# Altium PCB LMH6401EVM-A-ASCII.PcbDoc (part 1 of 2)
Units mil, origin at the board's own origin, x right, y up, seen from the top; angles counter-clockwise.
Board outline 1307 x 2660 mil, 6 copper layers (Top Layer L1, Layer 2 GND L2, Layer 3 V+ L3, Layer 4 V- L4, Layer 5 GND L5, Bottom Layer L6), stack 56.6 mil thick; 69 components, 33 nets, 203 pads, 373 vias.
Unrouted connection lines stored in the file: 2.
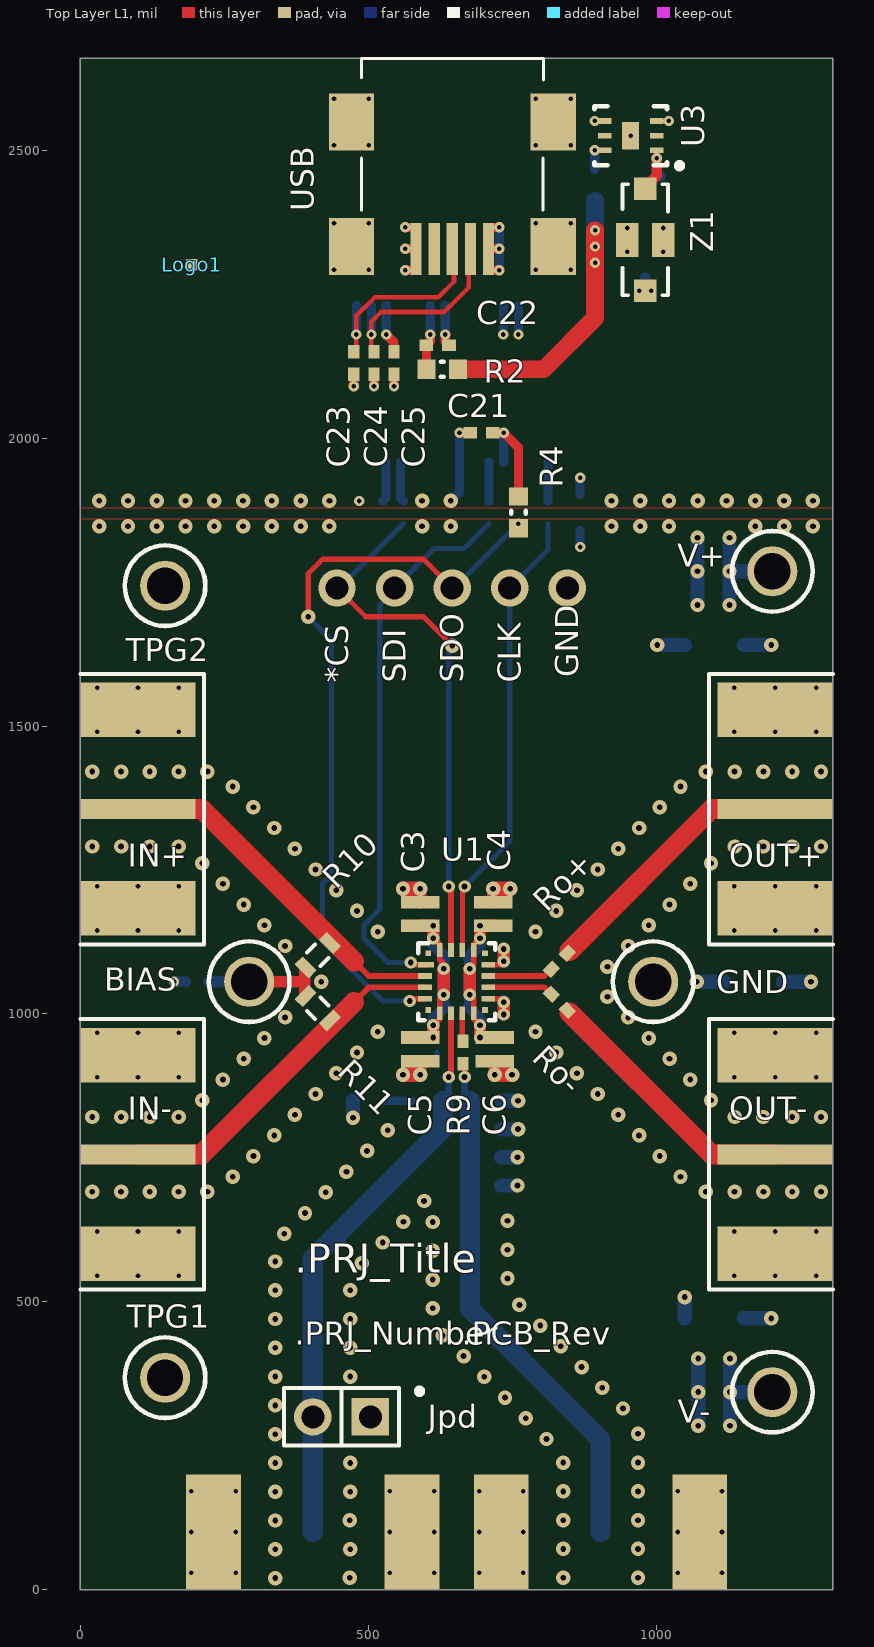
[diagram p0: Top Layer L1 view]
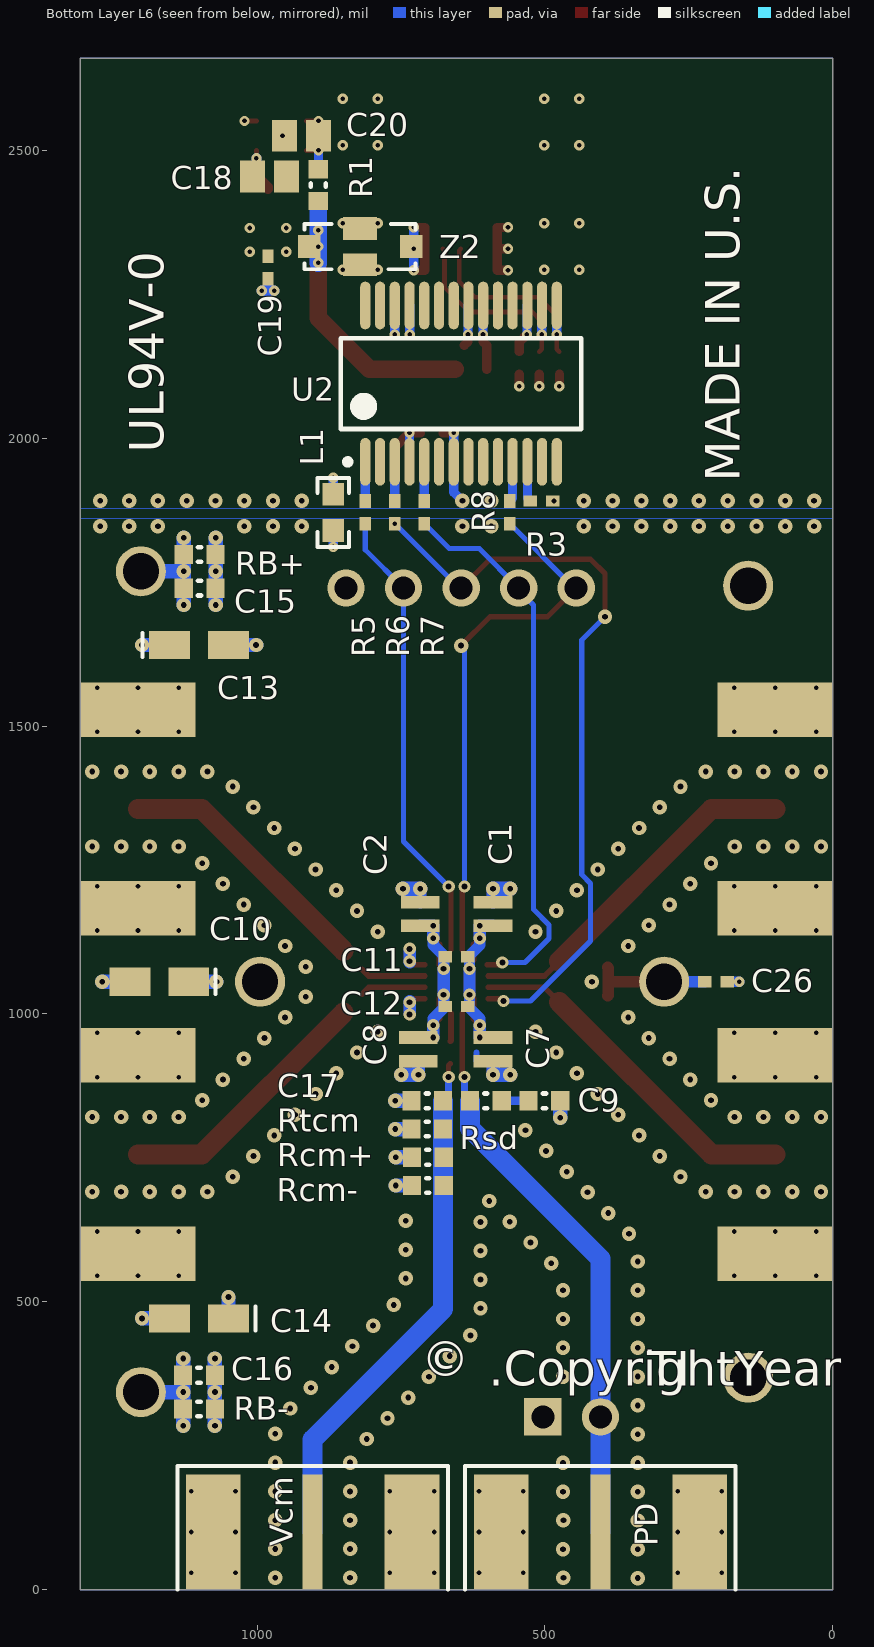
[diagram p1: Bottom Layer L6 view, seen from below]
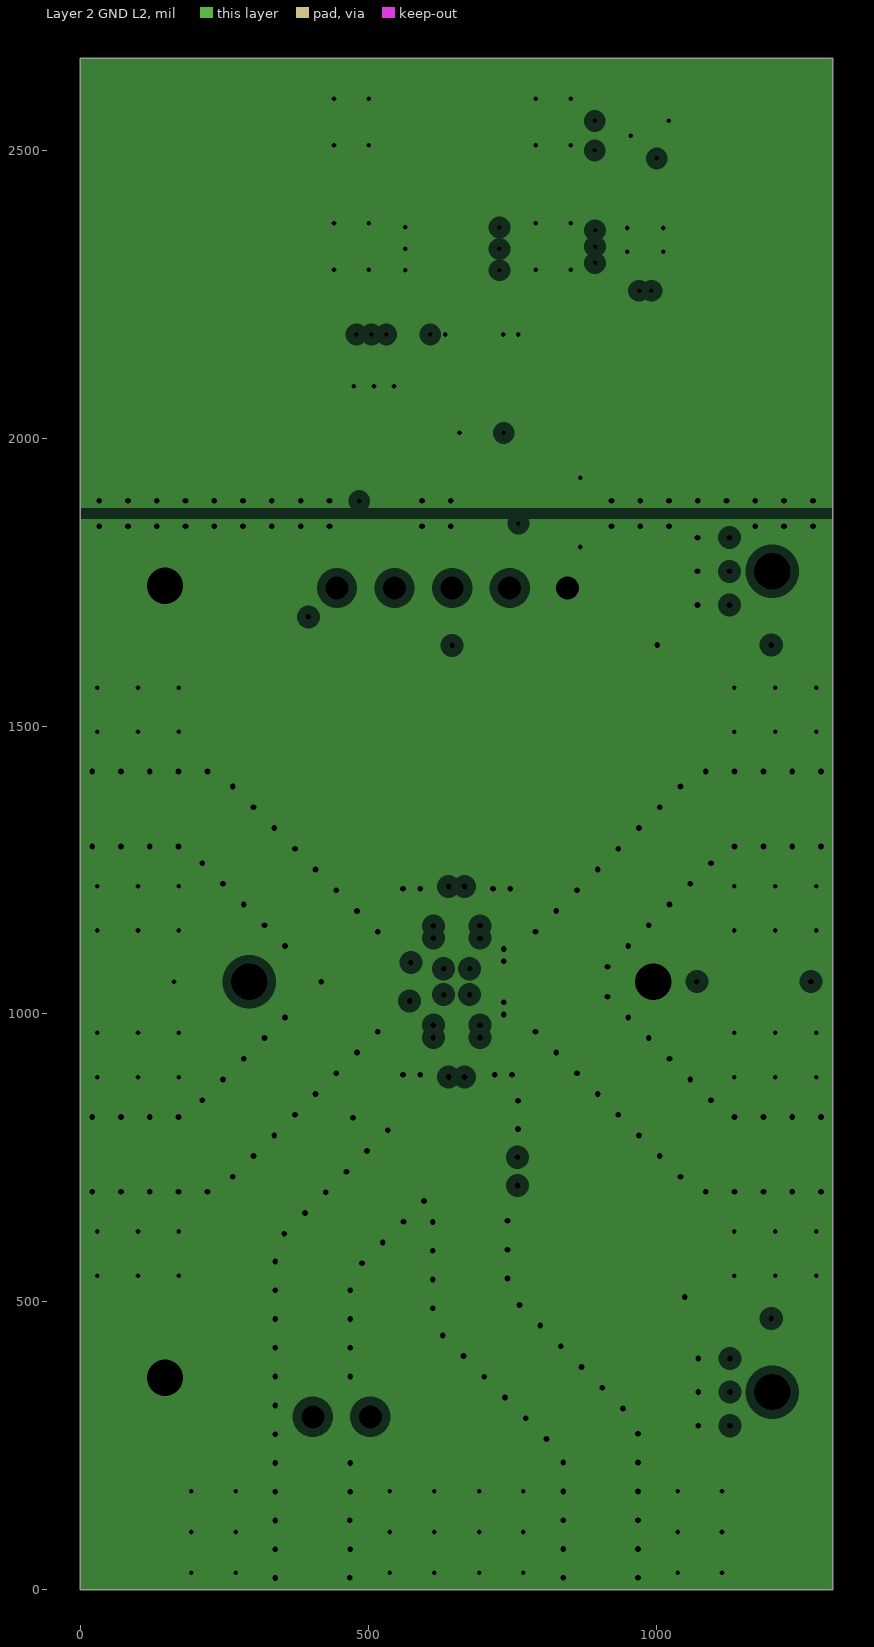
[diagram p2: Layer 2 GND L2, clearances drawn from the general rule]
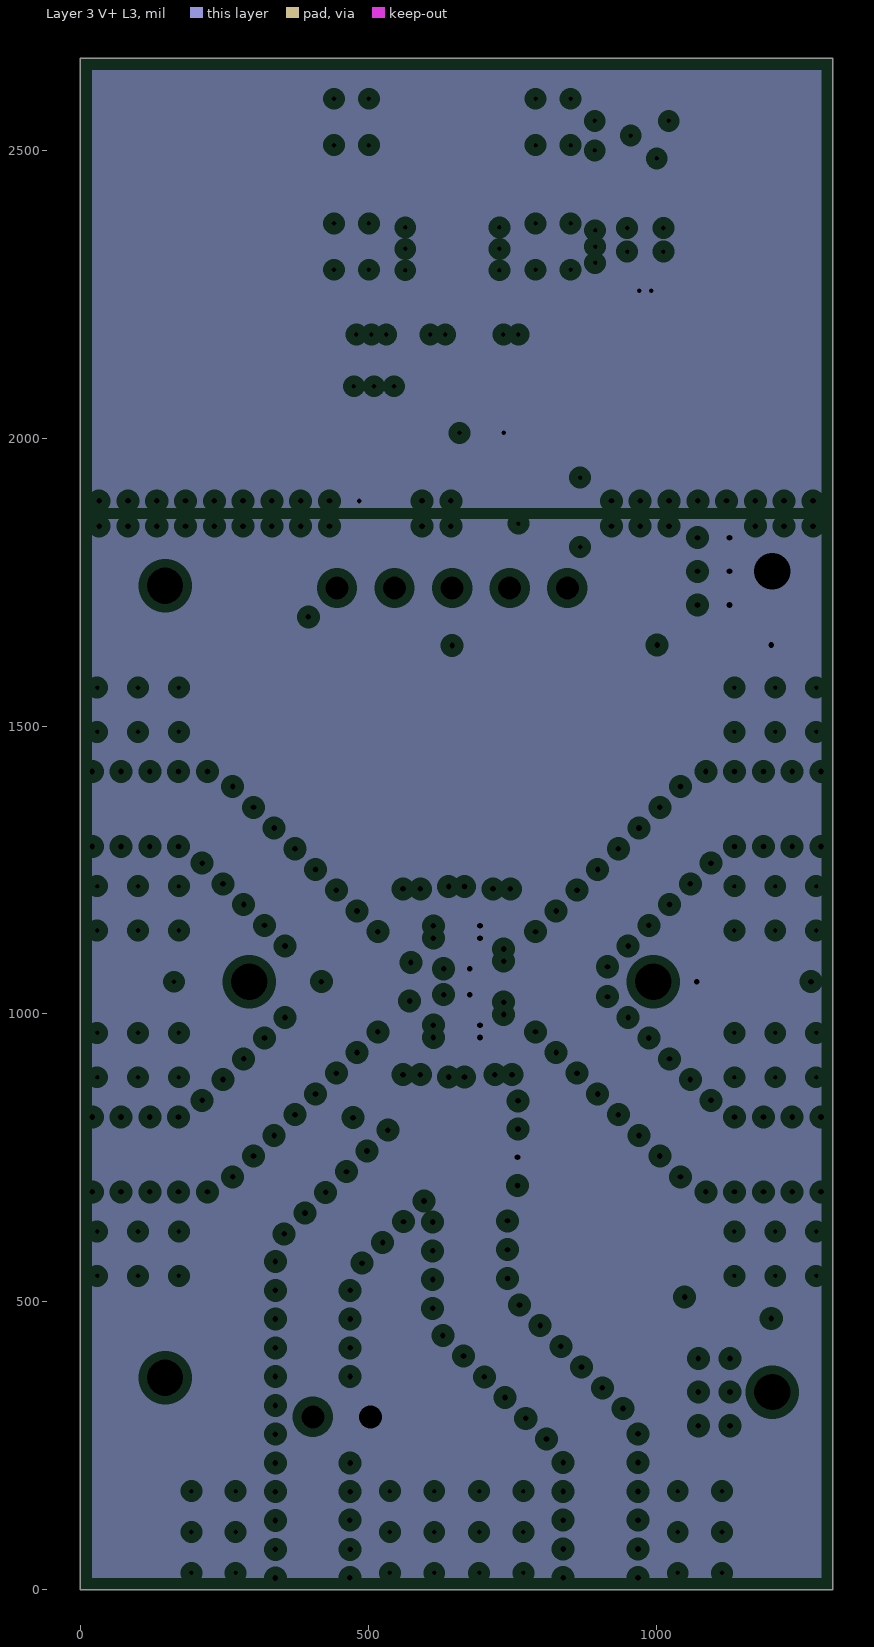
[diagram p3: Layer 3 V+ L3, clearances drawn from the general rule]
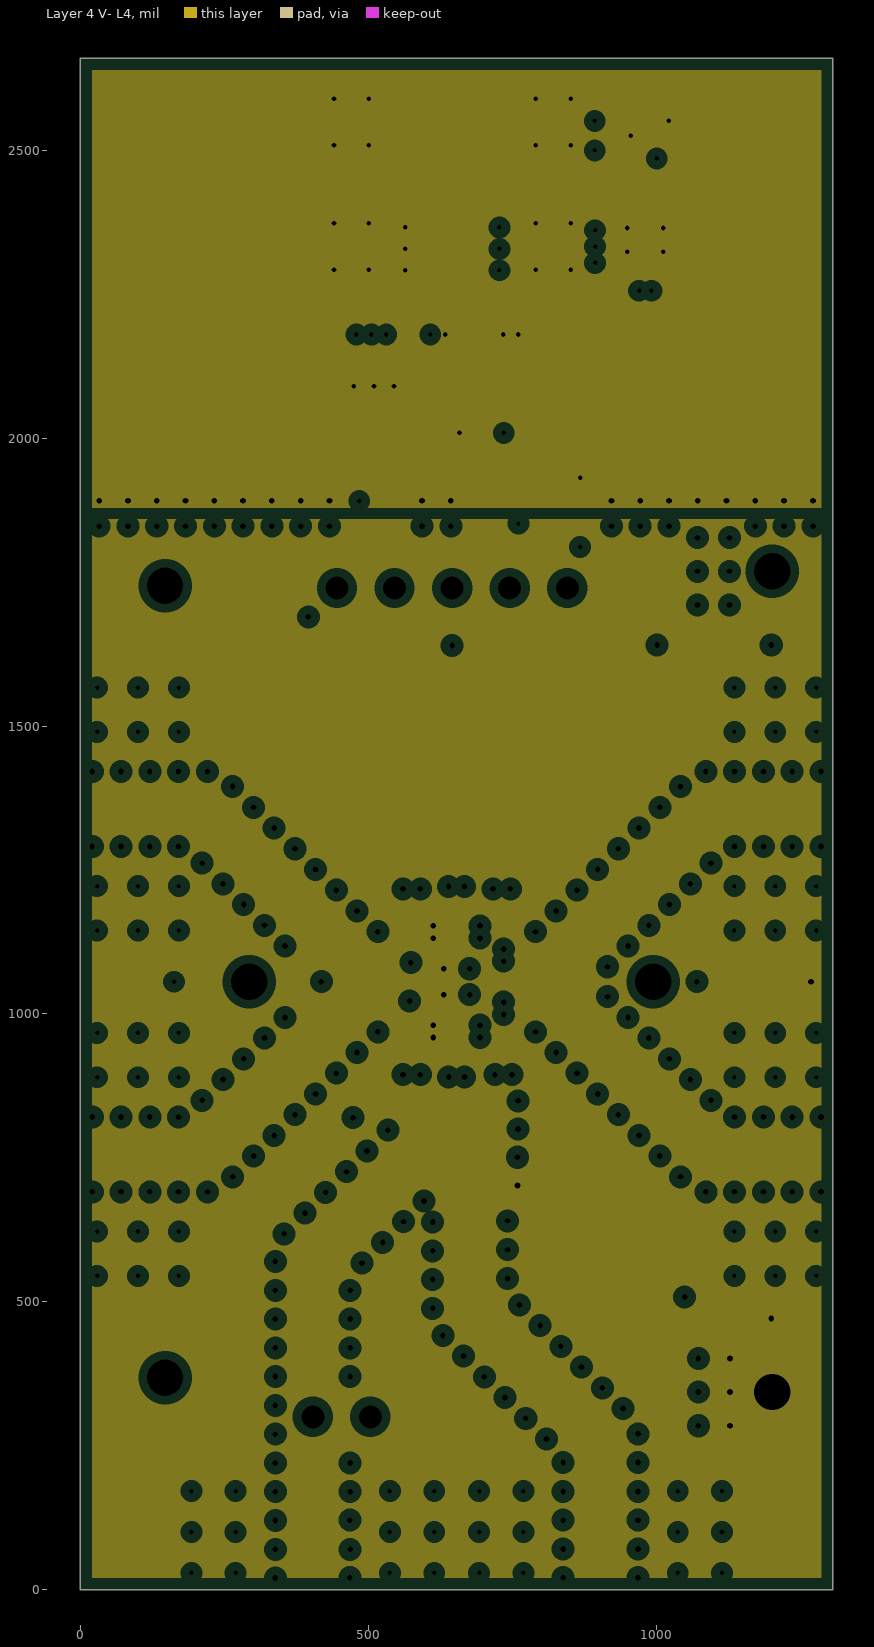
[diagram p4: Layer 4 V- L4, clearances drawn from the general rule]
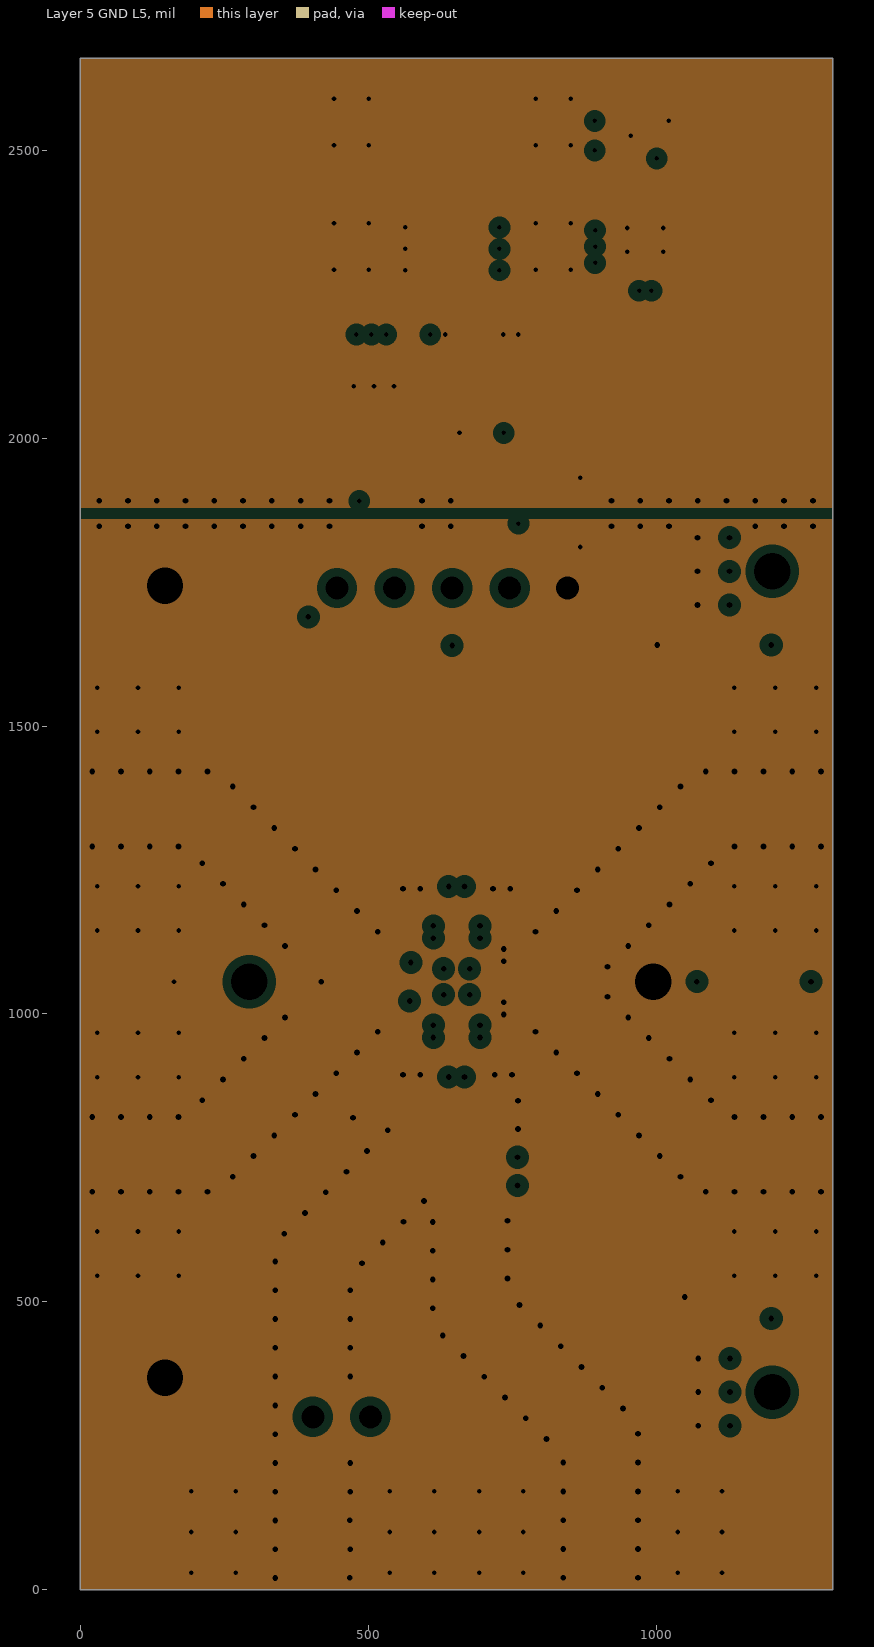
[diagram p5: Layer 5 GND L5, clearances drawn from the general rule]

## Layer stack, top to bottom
Top Solder: solder mask 0.4, Solder Resist, Dk 3.5
Top Layer L1: signal copper 1.4
Dielectric1: core 16.6, Rogers RO4350, Dk 3.66
Layer 2 GND L2: plane copper 1.4, net (Multiple Nets)
Dielectric2: prepreg 5, FR406, Dk 4.8
Layer 3 V+ L3: plane copper 1.4, net (Multiple Nets)
Dielectric4: core 5, FR406, Dk 4.8
Layer 4 V- L4: plane copper 1.4, net (Multiple Nets)
Dielectric5: prepreg 5, FR406, Dk 4.8
Layer 5 GND L5: plane copper 1.4, net (Multiple Nets)
Dielectric3: core 16.6, FR406, Dk 4.8
Bottom Layer L6: signal copper 1.4
Bottom Solder: solder mask 0.4, Solder Resist, Dk 3.5

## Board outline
0,0 1307,0 1307,2660 0,2660

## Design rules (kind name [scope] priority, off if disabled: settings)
AcuteAngle [All] p0: scope1count=1 scope1_0_kind=Board scope1_0_value=Board scope2count=1 scope2_0_kind=Board scope2_0_value=Board commentlength=0 minimum=4.50000000000000E+0001
AcuteAngle [All] p1: minimum=4.50000000000000E+0001 checktracksonly=FALSE
AssemblyTestPointUsage [All] p0: scope1count=1 scope1_0_kind=Board scope1_0_value=Board scope2count=1 scope2_0_kind=Board scope2_0_value=Board commentlength=0
AssemblyTestPointUsage [All] p1: valid=2
AssemblyTestpoint [All] p0: scope1count=1 scope1_0_kind=Board scope1_0_value=Board scope2count=1 scope2_0_kind=Board scope2_0_value=Board commentlength=0
Clearance Clearance_1 [All] p0 off: scope1count=1 scope1_0_kind=Board scope1_0_value=Board scope2count=1 scope2_0_kind=Board scope2_0_value=Board commentlength=145 gap=35 // Protel DXP Scope 2 Expression Was: (InNet('NetIN+_1') OR InNet('NetIN-_1') OR InNet('NetOUT-_1') OR InNet('NetOUT+_1') OR InNet('NetRtcm_1'))
Clearance Clearance_BoardEdge_MountingHoles [All] p0 off: scope1count=1 scope1_0_kind=Board scope1_0_value=Board scope2count=1 scope2_0_kind=Board scope2_0_value=Board commentlength=48 gap=40 // Protel DXP Scope 2 Expression Was: IsKeepOut
Clearance Clearance_BoardEdge_Poly [All] p0 off: scope1count=1 scope1_0_kind=Board scope1_0_value=Board scope2count=1 scope2_0_kind=Board scope2_0_value=Board commentlength=48 gap=25 // Protel DXP Scope 2 Expression Was: IsKeepOut
Clearance Clearance_BoardEdge [All] p0 off: scope1count=1 scope1_0_kind=Board scope1_0_value=Board scope2count=1 scope2_0_kind=Board scope2_0_value=Board commentlength=48 gap=75 // Protel DXP Scope 2 Expression Was: IsKeepOut
Clearance Clearance_Poly [All] p0 off: scope1count=1 scope1_0_kind=Board scope1_0_value=Board scope2count=1 scope2_0_kind=Board scope2_0_value=Board commentlength=48 gap=10 // Protel DXP Scope 1 Expression Was: InPolygon
Clearance [All] p0: scope1count=1 scope1_0_kind=Board scope1_0_value=Board scope2count=1 scope2_0_kind=Board scope2_0_value=Board commentlength=0 gap=5
Clearance Clearance_U2 [All] p0: scope1count=1 scope1_0_kind=Component scope1_0_value=U2 scope2count=1 scope2_0_kind=Board scope2_0_value=Board commentlength=0 gap=7.87
Clearance Clearance_2 [All] p0 off: scope1count=1 scope1_0_kind=Board scope1_0_value=Board scope2count=1 scope2_0_kind=Net scope2_0_value=NetJpd_2 commentlength=78 gap=35 // Protel DXP Scope 1 Expression Was: (InNamedPolygon('Bottom Layer L6-GND'))
Clearance Clearance_2 [(InNamedPolygon('Bottom Layer L6-GND')) vs InNet('NetJpd_2')] p1: gap=35
Clearance Clearance_1 [InNamedPolygon('Top Layer L1-GND') vs (InNet('NetIN+_1') OR InNet('NetIN-_1') OR InNet('NetOUT-_1') OR InNet('NetOUT+_1') OR InNet('NetRtcm_1'))] p2: gap=35
Clearance Clearance_U2 [InComponent('U2')] p3: gap=7.87
Clearance Clearance_BoardEdge_MountingHoles [OnCopper and InComponentClass('Mounting Holes') vs IsKeepOut] p4: gap=40
Clearance Clearance_BoardEdge_Poly [OnCopper and InPoly vs IsKeepOut] p5: gap=25
Clearance Clearance_BoardEdge [OnCopper and Not InComponentClass('Logo') and not InComponentClass('FiducialMark') and not InRegion(1000,500,4000,800) and Not IsKeepout vs IsKeepOut] p6: gap=75
Clearance Clearance_Poly [InPolygon] p7: gap=10
Clearance [All] p8: gap=5
ComponentClearance ComponentClearance_1 [All] p0 off: scope1count=1 scope1_0_kind=Board scope1_0_value=Board scope2count=1 scope2_0_kind=Board scope2_0_value=Board commentlength=188 gap=0 collisioncheckmode=3 // Protel DXP Scope 2 Expression Was: HasFootprint ('Emerson_142-0701-851*') or HasFootprint ('Keystone_1902C*') or HasFootprint ('NY PMS 440 0025 PH*') or HasFootprint ('Fiducial10-20*')
ComponentClearance ComponentClearance_Shunt [All] p0: scope1count=1 scope1_0_kind=ComponentClass scope1_0_value=Header scope2count=1 scope2_0_kind=ComponentClass scope2_0_value=Shunt commentlength=0 gap=0 collisioncheckmode=3
ComponentClearance ComponentClearance_Logo [All] p0: scope1count=1 scope1_0_kind=ComponentClass scope1_0_value=Logo scope2count=1 scope2_0_kind=Board scope2_0_value=Board commentlength=0 gap=50 collisioncheckmode=3
ComponentClearance ComponentClearance_ScrewToNut [All] p0 off: scope1count=1 scope1_0_kind=Board scope1_0_value=Board scope2count=1 scope2_0_kind=Board scope2_0_value=Board commentlength=71 gap=5 collisioncheckmode=3 // Protel DXP Scope 2 Expression Was: (HasFootprint('Keystone_1902C'))
ComponentClearance ComponentClearance_MountingHoles [All] p0: scope1count=1 scope1_0_kind=ComponentClass scope1_0_value="Mounting Holes" scope2count=1 scope2_0_kind=Board scope2_0_value=Board commentlength=0 gap=250 collisioncheckmode=3
ComponentClearance ComponentClearance_SmallPassives [All] p0 off: scope1count=1 scope1_0_kind=Board scope1_0_value=Board scope2count=1 scope2_0_kind=Board scope2_0_value=Board commentlength=620 gap=10 collisioncheckmode=3 // Protel DXP Scope 2 Expression Was: HasFootprint('0201*') or HasFootprint('0402*') or HasFootprint('0508') or HasFootprint('0603*') or HasFootprint('0612') or HasFootprint('0805*') or HasFootprint('0815*') or HasFootprint('0830*') or HasFootprint('1206*') or HasFootprint('1210*') or HasFootprint('1808*') or HasFootprint('1812*') or HasFootprint('1825*') or HasFootprint('2010*') or HasFootprint('2220*') or HasFootprint('2225*') or HasFootprint('2512*') or HasFootprint('2728*') or HasFootprint('3518*') or HasFootprint('FIL_NFM41P*') or HasFootprint('SDB06A*') or HasFootprint('0306*') or HasFootprint('RMZ0016A*')
ComponentClearance ComponentClearance_THtoSMT [All] p0 off: scope1count=1 scope1_0_kind=Board scope1_0_value=Board scope2count=1 scope2_0_kind=Board scope2_0_value=Board commentlength=53 gap=10 collisioncheckmode=3 // Protel DXP Scope 2 Expression Was: IsSMTComponent
ComponentClearance ComponentClearance_THtoTH [All] p0 off: scope1count=1 scope1_0_kind=Board scope1_0_value=Board scope2count=1 scope2_0_kind=Board scope2_0_value=Board commentlength=54 gap=75 collisioncheckmode=3 // Protel DXP Scope 2 Expression Was: IsThruComponent
ComponentClearance [All] p0: scope1count=1 scope1_0_kind=Board scope1_0_value=Board scope2count=1 scope2_0_kind=Board scope2_0_value=Board commentlength=0 gap=40 collisioncheckmode=3
ComponentClearance ComponentClearance_1 [HasFootprint ('Emerson_142-0701-851*') or HasFootprint ('Keystone_1902C*') or HasFootprint ('NY PMS 440 0025 PH*') or HasFootprint ('Fiducial10-20*') vs HasFootprint ('Emerson_142-0701-851*') or HasFootprint ('Keystone_1902C*') or HasFootprint ('NY PMS 440 0025 PH*') or HasFootprint ('Fiducial10-20*')] p1: gap=0 collisioncheckmode=3 verticalgap=10 showdistances=FALSE
ComponentClearance ComponentClearance_Shunt [InComponentClass('Header') vs InComponentClass('Shunt')] p2: gap=0 collisioncheckmode=3 verticalgap=0 showdistances=FALSE
ComponentClearance ComponentClearance_Logo [InComponentClass('Logo')] p3: gap=50 collisioncheckmode=3 verticalgap=10 showdistances=FALSE
ComponentClearance ComponentClearance_ScrewToNut [(HasFootprint('NY PMS 440 0025 PH')) vs (HasFootprint('Keystone_1902C'))] p4: gap=5 collisioncheckmode=3 verticalgap=10 showdistances=FALSE
ComponentClearance ComponentClearance_MountingHoles [InComponentClass('Mounting Holes')] p5: gap=250 collisioncheckmode=3 verticalgap=100000 showdistances=FALSE
ComponentClearance ComponentClearance_SmallPassives [HasFootprint('0201*') or HasFootprint('0402*') or HasFootprint('0508') or HasFootprint('0603*') or HasFootprint('0612') or HasFootprint('0805*') or HasFootprint('0815*') or HasFootprint('0830*') or HasFootprint('1206*') or HasFootprint('1210*') or HasFootprint('1808*') or HasFootprint('1812*') or HasFootprint('1825*') or HasFootprint('2010*') or HasFootprint('2220*') or HasFootprint('2225*') or HasFootprint('2512*') or HasFootprint('2728*') or HasFootprint('3518*') or HasFootprint('FIL_NFM41P*') or HasFootprint('SDB06A*') or HasFootprint('0306*') or HasFootprint('RMZ0016A*') vs HasFootprint('0201*') or HasFootprint('0402*') or HasFootprint('0508') or HasFootprint('0603*') or HasFootprint('0612') or HasFootprint('0805*') or HasFootprint('0815*') or HasFootprint('0830*') or HasFootprint('1206*') or HasFootprint('1210*') or HasFootprint('1808*') or HasFootprint('1812*') or HasFootprint('1825*') or HasFootprint('2010*') or HasFootprint('2220*') or HasFootprint('2225*') or HasFootprint('2512*') or HasFootprint('2728*') or HasFootprint('3518*') or HasFootprint('FIL_NFM41P*') or HasFootprint('SDB06A*') or HasFootprint('0306*') or HasFootprint('RMZ0016A*')] p6: gap=10 collisioncheckmode=3 verticalgap=10 showdistances=FALSE
ComponentClearance ComponentClearance_THtoSMT [IsThruComponent vs IsSMTComponent] p7: gap=10 collisioncheckmode=3 verticalgap=0 showdistances=FALSE
ComponentClearance ComponentClearance_THtoTH [IsThruComponent vs IsThruComponent] p8: gap=75 collisioncheckmode=3 verticalgap=30 showdistances=FALSE
ComponentClearance [All] p9: gap=40 collisioncheckmode=3 verticalgap=10 showdistances=FALSE
DiffPairsRouting [All] p0: scope1count=1 scope1_0_kind=Board scope1_0_value=Board scope2count=1 scope2_0_kind=Board scope2_0_value=Board commentlength=0
DiffPairsRouting [All] p1: maxlimit=100 minlimit=10 mostfreqgap=10 toplayer_minwidth=15 toplayer_maxwidth=15 toplayer_prefwidth=15 bottomlayer_minwidth=15 bottomlayer_maxwidth=15 bottomlayer_prefwidth=15 maxuncoupledlength=1000
FabricationTestPointUsage TestPointUsage [All] p0: scope1count=1 scope1_0_kind=Board scope1_0_value=Board scope2count=1 scope2_0_kind=Board scope2_0_value=Board commentlength=0 valid=2 allowmultiple=FALSE
FabricationTestPointUsage TestPointUsage [All] p1: valid=2 allowmultiple=FALSE
FabricationTestpoint Testpoint [All] p0: scope1count=1 scope1_0_kind=Board scope1_0_value=Board scope2count=1 scope2_0_kind=Board scope2_0_value=Board commentlength=0 side=3 testpointundercomponent=TRUE minsize=40 maxsize=100 preferedsize=60 minholesize=0 maxholesize=40 preferedholesize=32 testpointgrid=1
FabricationTestpoint Testpoint [All] p1: side=3 testpointundercomponent=TRUE minsize=40 maxsize=100 preferedsize=60 minholesize=0 maxholesize=40 preferedholesize=32 testpointgrid=1 allowsidetop=TRUE allowsidebottom=TRUE usegrid=TRUE gridtolerance=0.01
FanoutControl Fanout_LCC [All] p0 off: scope1count=1 scope1_0_kind=Board scope1_0_value=Board scope2count=1 scope2_0_kind=Board scope2_0_value=Board commentlength=69 // Protel DXP Scope 1 Expression Was: IsLCC   Fanout_LCC (Default Rule)
FanoutControl Fanout_BGA [All] p0 off: scope1count=1 scope1_0_kind=Board scope1_0_value=Board scope2count=1 scope2_0_kind=Board scope2_0_value=Board commentlength=69 // Protel DXP Scope 1 Expression Was: IsBGA   Fanout_BGA (Default Rule)
FanoutControl Fanout_SOIC [All] p0 off: scope1count=1 scope1_0_kind=Board scope1_0_value=Board scope2count=1 scope2_0_kind=Board scope2_0_value=Board commentlength=71 // Protel DXP Scope 1 Expression Was: IsSOIC   Fanout_SOIC (Default Rule)
FanoutControl Fanout_Default [All] p0: scope1count=1 scope1_0_kind=Board scope1_0_value=Board scope2count=1 scope2_0_kind=Board scope2_0_value=Board commentlength=30 // Fanout_Default (Default Rule)
FanoutControl Fanout_Small [All] p0 off: scope1count=1 scope1_0_kind=Board scope1_0_value=Board scope2count=1 scope2_0_kind=Board scope2_0_value=Board commentlength=84 // Protel DXP Scope 1 Expression Was: (CompPinCount < 5)   Fanout_Small (Default Rule)
FanoutControl Fanout_LCC [IsLCC] p1: bgadir=Out bgaviamode=Centered fanoutstyle=Auto fanoutdirection=Alternating viagrid=1 // Fanout_LCC (Default Rule)
FanoutControl Fanout_BGA [IsBGA] p2: bgadir=Out bgaviamode=Centered fanoutstyle=Auto fanoutdirection=Alternating viagrid=1 // Fanout_BGA (Default Rule)
FanoutControl Fanout_Default [All] p4: bgadir=Out bgaviamode=Centered fanoutstyle=Auto fanoutdirection=Alternating viagrid=1 // Fanout_Default (Default Rule)
FanoutControl Fanout_Small [(CompPinCount < 5)] p5: bgadir=Out bgaviamode=Centered fanoutstyle=Auto fanoutdirection=OutThenIn viagrid=1 // Fanout_Small (Default Rule)
Height [All] p0: scope1count=1 scope1_0_kind=Board scope1_0_value=Board scope2count=1 scope2_0_kind=Board scope2_0_value=Board commentlength=0
HoleSize [All] p0: scope1count=1 scope1_0_kind=Board scope1_0_value=Board scope2count=1 scope2_0_kind=Board scope2_0_value=Board commentlength=0 absolutevalues=TRUE maxlimit=251 minlimit=8 maxpercent=80.000 minpercent=20.000
HoleSize [All] p1: absolutevalues=TRUE maxlimit=251 minlimit=8 maxpercent=80.000 minpercent=20.000
HoleToHoleClearance [All] p0: scope1count=1 scope1_0_kind=Board scope1_0_value=Board scope2count=1 scope2_0_kind=Board scope2_0_value=Board commentlength=0
LayerPairs [All] p0: scope1count=1 scope1_0_kind=Board scope1_0_value=Board scope2count=1 scope2_0_kind=Board scope2_0_value=Board commentlength=0 enforce=TRUE
MinimumAnnularRing MinimumAnnularRing_ThermalPadVias [All] p0 off: scope1count=1 scope1_0_kind=Board scope1_0_value=Board scope2count=1 scope2_0_kind=Board scope2_0_value=Board commentlength=63 minimumring=5 // Protel DXP Scope 1 Expression Was: IsVia and InAnyComponent
MinimumAnnularRing [All] p0: scope1count=1 scope1_0_kind=Board scope1_0_value=Board scope2count=1 scope2_0_kind=Board scope2_0_value=Board commentlength=0 minimumring=5
MinimumAnnularRing MinimumAnnularRing_ThermalPadVias [IsVia and InAnyComponent] p1: minimumring=5
MinimumAnnularRing [All] p2: minimumring=5
MinimumSolderMaskSliver MinimumSolderMaskSliver_Logo [All] p0: scope1count=1 scope1_0_kind=ComponentClass scope1_0_value=Logo scope2count=1 scope2_0_kind=ComponentClass scope2_0_value=Logo commentlength=0
MinimumSolderMaskSliver [All] p0: scope1count=1 scope1_0_kind=Board scope1_0_value=Board scope2count=1 scope2_0_kind=Board scope2_0_value=Board commentlength=0
MinimumSolderMaskSliver MinimumSolderMaskSliver_Logo [InComponentClass('Logo') vs InComponentClass('Logo')] p1: minsoldermaskwidth=0.7
MinimumSolderMaskSliver [All] p2: minsoldermaskwidth=3.84
NetAntennae [All] p0: scope1count=1 scope1_0_kind=Board scope1_0_value=Board scope2count=1 scope2_0_kind=Board scope2_0_value=Board commentlength=0
PasteMaskExpansion [All] p0: scope1count=1 scope1_0_kind=Board scope1_0_value=Board scope2count=1 scope2_0_kind=Board scope2_0_value=Board commentlength=0 expansion=0
PlaneClearance [All] p0: scope1count=1 scope1_0_kind=Board scope1_0_value=Board scope2count=1 scope2_0_kind=Board scope2_0_value=Board commentlength=0 clearance=15
PlaneClearance [All] p1: clearance=15
PlaneConnect [All] p0: scope1count=1 scope1_0_kind=Board scope1_0_value=Board scope2count=1 scope2_0_kind=Board scope2_0_value=Board commentlength=0 planeconnectstyle=Direct reliefexpansion=10 reliefentries=4 reliefconductorwidth=10 reliefairgap=10
PlaneConnect [All] p1: planeconnectstyle=Direct reliefexpansion=10 reliefentries=4 reliefconductorwidth=10 reliefairgap=10
PolygonConnect [All] p0: scope1count=1 scope1_0_kind=Board scope1_0_value=Board scope2count=1 scope2_0_kind=Board scope2_0_value=Board commentlength=0 connectstyle=Direct reliefconductorwidth=10 reliefentries=4 polygonreliefangle="90 Angle"
PolygonConnect [All] p1: connectstyle=Direct reliefconductorwidth=10 reliefentries=4 polygonreliefangle="90 Angle" airgapwidth=10
RoutingCorners [All] p0: scope1count=1 scope1_0_kind=Board scope1_0_value=Board scope2count=1 scope2_0_kind=Board scope2_0_value=Board commentlength=0 cornerstyle=45-Degree minsetback=100 maxsetback=100
RoutingLayers [All] p0: scope1count=1 scope1_0_kind=Board scope1_0_value=Board scope2count=1 scope2_0_kind=Board scope2_0_value=Board commentlength=0 top layer=Automatic bottom layer=Automatic
RoutingPriority [All] p0: scope1count=1 scope1_0_kind=Board scope1_0_value=Board scope2count=1 scope2_0_kind=Board scope2_0_value=Board commentlength=0
RoutingTopology [All] p0: scope1count=1 scope1_0_kind=Board scope1_0_value=Board scope2count=1 scope2_0_kind=Board scope2_0_value=Board commentlength=0 topology=Shortest
RoutingVias ThermalPadVias [All] p0 off: scope1count=1 scope1_0_kind=Board scope1_0_value=Board scope2count=1 scope2_0_kind=Board scope2_0_value=Board commentlength=63 holewidth=7.87 width=19.68 viastyle="Through Hole" minholewidth=8 minwidth=18 maxholewidth=12.99 maxwidth=23.62 // Protel DXP Scope 1 Expression Was: IsVia and InAnyComponent
RoutingVias [All] p0: scope1count=1 scope1_0_kind=Board scope1_0_value=Board scope2count=1 scope2_0_kind=Board scope2_0_value=Board commentlength=0 holewidth=16 width=34 viastyle="Through Hole" minholewidth=8 minwidth=18 maxholewidth=40 maxwidth=65
RoutingVias ThermalPadVias [IsVia and InAnyComponent] p1: holewidth=7.87 width=19.68 viastyle="Through Hole" minholewidth=8 minwidth=18 maxholewidth=12.99 maxwidth=23.62
RoutingVias [All] p2: holewidth=16 width=34 viastyle="Through Hole" minholewidth=8 minwidth=18 maxholewidth=40 maxwidth=65
SMDToCorner [All] p0: scope1count=1 scope1_0_kind=Board scope1_0_value=Board scope2count=1 scope2_0_kind=Board scope2_0_value=Board commentlength=0 distance=30000
SMDToCorner [All] p1: distance=30000
ShortCircuit [All] p0: scope1count=1 scope1_0_kind=Board scope1_0_value=Board scope2count=1 scope2_0_kind=Board scope2_0_value=Board commentlength=0 allowed=FALSE
SilkToBoardRegionClearance [All] p0: scope1count=1 scope1_0_kind=Board scope1_0_value=Board scope2count=1 scope2_0_kind=Board scope2_0_value=Board commentlength=0
SilkToSilkClearance [All] p0: scope1count=1 scope1_0_kind=Board scope1_0_value=Board scope2count=1 scope2_0_kind=Board scope2_0_value=Board commentlength=0
SilkToSilkClearance [All] p1: silktosilkclearance=5
SilkToSolderMaskClearance SilkscreenOverComponentPads [All] p0 off: scope1count=1 scope1_0_kind=Board scope1_0_value=Board scope2count=1 scope2_0_kind=Board scope2_0_value=Board commentlength=44 // Protel DXP Scope 1 Expression Was: IsPad
SilkToSolderMaskClearance SilkscreenOverComponentPads [IsPad] p1: minsilkscreentomaskgap=5 clearancetoexposedcopper=TRUE
SolderMaskExpansion [All] p0: scope1count=1 scope1_0_kind=Board scope1_0_value=Board scope2count=1 scope2_0_kind=Board scope2_0_value=Board commentlength=0 expansion=1.97
SolderMaskExpansion [All] p1: expansion=1.97
UnRoutedNet [All] p0: scope1count=1 scope1_0_kind=Board scope1_0_value=Board scope2count=1 scope2_0_kind=Board scope2_0_value=Board commentlength=0
UnpouredPolygon [All] p0: scope1count=1 scope1_0_kind=Board scope1_0_value=Board scope2count=1 scope2_0_kind=Board scope2_0_value=Board commentlength=0
UnpouredPolygon [All] p1: allowunpoured=FALSE
Width [All] p0: scope1count=1 scope1_0_kind=Board scope1_0_value=Board scope2count=1 scope2_0_kind=Board scope2_0_value=Board commentlength=0 maxlimit=100 minlimit=6 preferedwidth=10
Width [All] p1: maxlimit=100 minlimit=6 preferedwidth=10 checkconnectedcopper=TRUE
14 further rules are at their usual default settings.

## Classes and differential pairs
component class Logo: Logo1
component class AssemblyNote: ZZ2 ZZ3 ZZ4
component class Header: Jpd

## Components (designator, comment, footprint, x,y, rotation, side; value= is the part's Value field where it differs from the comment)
BIAS "5012" Keystone5012 293,1056 r0 top
C1 "LLL185R71E103MA01L" 0306 590.34,1173.48 r270 bottom
C2 "LLL185R71E103MA01L" 0306 716.87,1173.48 r90 bottom
C3 "LLL185R71H222MA01L" 0306 590.34,1173.48 r90 top
C4 "LLL185R71H222MA01L" 0306 716.87,1173.48 r270 top
C5 "LLL185R71H222MA01L" 0306 590.34,938.52 r270 top
C6 "LLL185R71H222MA01L" 0306 719.87,938.52 r90 top
C7 "LLL185R71E103MA01L" 0306 590.34,938.52 r90 bottom
C8 "LLL185R71E103MA01L" 0306 719.87,938.52 r270 bottom
C9 "GRM188R71C103KA01D" 0603L 501,849 r180 bottom
C10 "TPSA106K010R0900" 3216-18 1170,1056 r0 bottom
C11 "C1005X5R1A104K" 0402L 653.6,1099.1 r0 bottom
C12 "C1005X5R1A104K" 0402L 653.6,1012.9 r0 bottom
C13 "TPSA106K010R0900" 3216-18 1101,1641 r180 bottom
C14 "TPSA106K010R0900" 3216-18 1101,471 r0 bottom
C15 "Used in BOM report" 0603L 1100,1739.77 r180 bottom
C16 "Used in BOM report" 0603L 1101,372.23 r180 bottom
C17 "GRM188R71C103KA01D" 0603L 704.5,849 r0 bottom
C18 "EMK212BJ106KG-T" 0805L 978.51,2455 r180 bottom
C19 "C1005X5R1A104K" 0402L 981.25,2296.91 r270 bottom
C20 "EMK212BJ106KG-T" 0805L 923.06,2525.9 r0 bottom
C21 "C1005X7R1C103K" 0402L 696.93,2009.51 r180 top
C22 "C1005X7R1C103K" 0402L 620.66,2161.64 r0 top
C23 "GRM1555C1H470JZ01" 0402L 474.96,2131 r270 top
C24 "GRM1555C1H470JZ01" 0402L 509.96,2131 r270 top
C25 "C1005X5R1A104K" 0402L 544.75,2131 r90 top
C26 "C1005X5R1A104K" 0402L 203,1056 r0 bottom
GND "5011" Keystone5011 995,1056 r0 top
IN+ "142-0701-851" Emerson_142-0701-851#1 100,1356 r90 top
IN- "142-0701-851" Emerson_142-0701-851#1 100,756 r90 top
Jpd "TSW-102-07-G-S" TSW-102-07-G-S 453.6,300 r180 top
L1 "BLM18SG331TN1D" 0603 868,1871.5 r90 bottom
Logo1 "Texas Instruments" TI_Stacked_SolderMask_Small_Vertical 192,2300 r0 top
OUT+ "142-0701-851" Emerson_142-0701-851#1 1207,1356 r270 top
OUT- "142-0701-851" Emerson_142-0701-851#1 1207,756 r270 top
PD "142-0701-851" Emerson_142-0701-851#2 403.6,100 r0 bottom
R1 "CRCW06030000Z0EA" 0603L 894.03,2440 r270 bottom
R2 "CRCW06030000Z0EA" 0603L 628.53,2120 r180 top
R3 "CRCW040210K0FKED" 0402L 505.91,1891.18 r180 bottom
R4 "CRCW0603301RFKEA" 0603L 760.91,1871.5 r90 top
R5 "CRCW040222R1FKED" 0402L 812.09,1871.5 r90 bottom
R6 "CRCW040222R1FKED" 0402L 760.91,1871.5 r90 bottom
R7 "CRCW040222R1FKED" 0402L 709.72,1871.5 r90 bottom
R8 "CRCW040222R1FKED" 0402L 561.18,1871.5 r90 bottom
R9 "ERJ-2GE0R00X" 0402L 664.5,933 r90 top
R10 "CRCW060310K0FKEA" 0603S 412.26,1102 r45 top
R11 "CRCW060310K0FKEA" 0603S 412.26,1010 r135 top
RB+ "Used in BOM report" 0603L 1100,1798.23 r0 bottom
RB- "Used in BOM report" 0603L 1101,313.77 r180 bottom
Rcm+ "CRCW06031K00FKEA" 0603L 703.5,751 r0 bottom
Rcm- "CRCW06031K00FKEA" 0603L 703.5,702 r180 bottom
Ro+ "CRCW040240R2FKED" 0402L 831.93,1091.61 r45 top
Ro- "CRCW040240R2FKED" 0402L 831.93,1020.39 r315 top
Rsd "CRCW060349R9FKEA" 0603L 602.71,849 r0 bottom
Rtcm "Used in BOM report" 0603L 704.5,800 r0 bottom
TPG1 "5011" Keystone5011 147,368 r0 top
TPG2 "5011" Keystone5011 147,1744 r0 top
U1 "LMH6401IRMZR" RMZ0016A 653.6,1056 r0 top
U2 "FT245RL" SSOP28_N 645.75,2095 r90 bottom
U3 "LP5900SD-1.8/NOPB" SDB06A 956.02,2525.9 r180 top
USB "651-305-142-821" CONN_USB-MINI-AB-651-305-142-821 646,2439.53 r180 top
V+ "5010" Keystone5010 1202,1769 r0 top
V- "5014" Keystone5014 1202,343 r0 top
Vcm "142-0701-851" Emerson_142-0701-851#2 903.6,100 r0 bottom
Z1 "NFM41PC204F1H3L" FIL_NFM41P 981.25,2345 r90 top
Z2 "NFM41PC204F1H3L" FIL_NFM41P 821.2,2333.23 r180 bottom
ZZ2 "These assemblies are ESD sensitive, ESD precautions shall be observed." AssemblyNote 185,3829.11 r0 top
ZZ3 "These assemblies must be clean and free from flux and all contaminants. Use of no clean flux is not acceptable." AssemblyNote 185,3740.56 r0 top
ZZ4 "These assemblies must comply with workmanship standards IPC-A-610 Class 2, unless otherwise specified." AssemblyNote 185,3652 r0 top

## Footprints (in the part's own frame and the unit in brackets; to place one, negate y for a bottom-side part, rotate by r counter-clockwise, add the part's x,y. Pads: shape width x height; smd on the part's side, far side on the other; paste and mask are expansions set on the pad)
0306 [mil] "bxl footprint"
  rect 22x67 smd: 1(-20.5,0) 2(20.5,0)
0402L [mm] "0402 from SM-752 data"
  rect 0.6x0.5 smd: 1(-0.5,0) 2(0.5,0)
0603 [mm] "0603 from SM-752 data"
  rect 1x0.95 smd: 1(-0.8,0) 2(0.8,0)
  silkscreen extent -1.52,-0.69 1.52,0.69
0603L [mm] "0603 from SM-752 data"
  rect 0.8x0.85 smd: 1(-0.7,0) 2(0.7,0)
  silkscreen extent -0.07,-0.33 0.07,0.33
0603S [mil]
  rect 20x35 smd: 1(-30,0) 2(30,0)
  silkscreen extent -10,-17 10,17
0805L [mm] "0805 from SM-752 data"
  rect 1.1x1.4 smd: 1(-0.75,0) 2(0.75,0)
3216-18 [mm] "Medium density IPC, based on Kemet T495 dimensions"
  rect 1.8x1.25 smd: 1(-1.3,0) 2(1.3,0)
  silkscreen extent -2.49,-0.54 -2.49,0.54
AssemblyNote [mil] "Assembly Note"
CONN_USB-MINI-AB-651-305-142-821 [mm] "WE-USB2-MINI-AB TYPE"
  rect 0.5x2.3 smd: 1(-1.6,2.8) 2(-0.8,2.8) 3(0,2.8) 4(0.8,2.8) 5(1.6,2.8)
  rect 2x2.5 smd: 6(4.45,2.7) 7(4.45,-2.8) 8(-4.45,-2.8) 9(-4.45,2.7)
  silkscreen extent -4.03,-5.6 4,1.1
Emerson_142-0701-851#1 [mil] "Johnson Components"
  rect 35x200 smd mask+3: 1(0,0)
  rect 95x200 smd: 2(-172.5,0) 3(172.5,0)
  rect 95x200 smd far side: 4(172.5,0) 5(-172.5,0)
  silkscreen extent -235,-115 235,100
Emerson_142-0701-851#2 [mil] "Johnson Components"
  rect 35x200 smd: 1(0,0)
  rect 95x200 smd: 2(-172.5,0) 3(172.5,0)
  rect 95x200 smd far side: 4(172.5,0) 5(-172.5,0)
  silkscreen extent -235,-115 235,100
FIL_NFM41P [mm] "FILTER LC HIGH FREQ .2UF 1806"
  rect 1x1 smd: 1(-2.25,0) 3(2.25,0)
  rect 1.5x1 smd: 2(0,0.8) 2(0,-0.8)
  silkscreen extent -2.45,-1 2.45,1
Keystone5010 [mil] "Keystone Multipurpose loops"
  round 87 hole 63: 1(0,0)
  silkscreen extent -70,-70 70,70
Keystone5011 [mil] "Keystone Multipurpose loops"
  round 87 hole 63: 1(0,0)
  silkscreen extent -70,-70 70,70
Keystone5012 [mil] "Keystone Multipurpose loops"
  round 87 hole 63: 1(0,0)
  silkscreen extent -70,-70 70,70
Keystone5014 [mil] "Keystone Multipurpose loops"
  round 87 hole 63: 1(0,0)
  silkscreen extent -70,-70 70,70
RMZ0016A [mm] "QFN, 16-Leads, Body 3.0x3.0 mm, Pitch 0.5mm"
  rrect0% 0.7x0.25 smd paste+0 mask+0.062: 1(-1.35,0.75)
  rrect0% 0.6x0.25 smd paste+0 mask+0.062: 2(-1.4,0.25) 3(-1.4,-0.25) 4(-1.4,-0.75) 9(1.4,-0.75) 10(1.4,-0.25) 11(1.4,0.25) 12(1.4,0.75)
  rrect0% 0.25x0.6 smd paste+0 mask+0.062: 5(-0.75,-1.4) 6(-0.25,-1.4) 7(0.25,-1.4) 8(0.75,-1.4) 13(0.75,1.4) 14(0.25,1.4) 15(-0.25,1.4) 16(-0.75,1.4)
  rrect0% 0.25x0.25 smd paste+0 mask+0.062: ""(-1.25,-1.25) ""(-1.25,1.25) ""(1.25,-1.25) ""(1.25,1.25)
  silkscreen extent -1.7,-1.7 1.7,1.7
SDB06A [mm] "SON, 6-Leads, Body 2.2x2.5mm, Pitch 0.65mm, NSC Recommended (SC-70 Land)"
  rect 0.6x0.25 smd paste-0.125 mask+0.051: 1(-1.15,0.65) 2(-1.15,0) 3(-1.15,-0.65) 4(1.15,-0.65) 5(1.15,0) 6(1.15,0.65)
  rect 0.75x1.2 smd paste-0.6 mask+0.051: 7(0,0)
  silkscreen extent -2.28,-1.3 1.6,1.45
SSOP28_N [mm] "SOP, 28-Leads, Body 10.2x5.3mm, Pitch 0.65mm, IPC Medium Density"
  oval 2.1x0.45 smd: 1(-3.45,4.225) 2(-3.45,3.575) 3(-3.45,2.925) 4(-3.45,2.275) 5(-3.45,1.625) 6(-3.45,0.975) 7(-3.45,0.325) 8(-3.45,-0.325) 9(-3.45,-0.975) 10(-3.45,-1.625) 11(-3.45,-2.275) 12(-3.45,-2.925) 13(-3.45,-3.575) 14(-3.45,-4.225) 15(3.45,-4.225) 16(3.45,-3.575) 17(3.45,-2.925) 18(3.45,-2.275) 19(3.45,-1.625) 20(3.45,-0.975) 21(3.45,-0.325) 22(3.45,0.325) 23(3.45,0.975) 24(3.45,1.625) 25(3.45,2.275) 26(3.45,2.925) 27(3.45,3.575) 28(3.45,4.225)
  silkscreen extent -3.57,-5.3 2,5.3
TI_Stacked_SolderMask_Small_Vertical [mil]
  rect 20x20 smd paste-125 mask-125: 0(1.25,1.75)
TSW-102-07-G-S [mm] "Samtec 100mil, 1x2, 230 mil above insulator"
  rect 1.65x1.65 hole 1.016 mask+0: 1(-1.27,0)
  round 1.65 hole 1.016 mask+0: 2(1.27,0)
  silkscreen extent -3.57,-1.27 2.54,1.27

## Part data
BIAS: "Test Point, Multipurpose, White, TH"
C1 C2 C7 C8: "CAP, CERM, 0.01uF, 25V, +/-20%, X7R, 0306"
C3 C4 C5 C6: "CAP, CERM, 2200pF, 50V, +/-20%, X7R, 0306"
C9 C17: "CAP, CERM, 0.01uF, 16V, +/-10%, X7R, 0603"
C10 C13 C14: "CAP, TA, 10uF, 10V, +/-10%, 0.9 ohm, SMD"
C11 C12 C19 C25 C26: "CAP, CERM, 0.1uF, 10V, +/-10%, X5R, 0402"
C15 C16: library part Capacitor, "CAP, CERM, xxxF, xxV, [TempCo], xx%, [PackageReference]"
C18 C20: "CAP, CERM, 10uF, 16V, +/-10%, X5R, 0805"
C21 C22: "CAP, CERM, 0.01uF, 16V, +/-10%, X7R, 0402"
C23 C24: "CAP, CERM, 47pF, 50V, +/-5%, C0G/NP0, 0402"
GND TPG1 TPG2: "Test Point, TH, Multipurpose, Black"
IN+ IN- OUT+ OUT- PD Vcm: "Connector, SMT, End launch SMA 50 ohm"
Jpd: "Header, TH, 100mil, 2x1, Gold plated, 230 mil above insulator"
L1: "1.5A Ferrite Bead, 330 ohm @ 100MHz, SMD"
Logo1: library part TI_Logo, "Texas Instrument Corporate Signature"
R1 R2: "RES, 0 ohm, 5%, 0.1W, 0603"
R3: "RES, 10.0k ohm, 1%, 0.063W, 0402"
R4: "RES, 301 ohm, 1%, 0.1W, 0603"
R5 R6 R7 R8: "RES, 22.1 ohm, 1%, 0.063W, 0402"
R9: "RES, 0 ohm, 5%, 0.063W, 0402"
R10 R11: "RES, 10.0k ohm, 1%, 0.1W, 0603"
RB+ RB- Rtcm: library part Resistor, "RES, xxx ohm, x%, xW, [PackageReference]"
Rcm+ Rcm-: "RES, 1.00k ohm, 1%, 0.1W, 0603"
Ro+ Ro-: "RES, 40.2 ohm, 1%, 0.063W, 0402"
Rsd: "RES, 49.9 ohm, 1%, 0.1W, 0603"
U1: "5 GHz Ultra Wideband Digital Variable Gain Amplifier, RMZ0016A"
U2: "USB FIFO IC, 28SSOP"
U3: "Ultra Low Noise, 150mA Linear Regulator for RF/Analog Circuits Requires No Bypass Capacitor, 6-pin LLP, Pb-Free"
USB: "MINI USB 2.0 SMT TYPE AB 5 CONTACTS R/A, SMD"
V+: "Test Point, TH, Multipurpose, Red"
V-: "Test Point, Multipurpose, Yellow, TH"
Z1 Z2: "Filter, LC, 0.2uF, 1806, SMT"
ZZ2 ZZ3 ZZ4: library part AssemblyNote

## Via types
v1: diameter 25, hole 10, Top Layer L1 to Bottom Layer L6, tented both sides, 221 vias
v2: diameter 18, hole 8, Top Layer L1 to Bottom Layer L6, tented top, 73 vias
v3: diameter 18, hole 8, Top Layer L1 to Bottom Layer L6, tented both sides, 52 vias
v4: diameter 21.46, hole 10, Top Layer L1 to Bottom Layer L6, tented both sides, 22 vias
v5: diameter 64.96, hole 40, Top Layer L1 to Bottom Layer L6, 5 vias

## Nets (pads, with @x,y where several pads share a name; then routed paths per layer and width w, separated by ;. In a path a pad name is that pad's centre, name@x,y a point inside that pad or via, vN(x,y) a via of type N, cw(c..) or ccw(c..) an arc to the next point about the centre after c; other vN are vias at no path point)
\CS: R8.1 U1.15 | length 932.5
  Top Layer L1 w9: v5(445.75,1740) 495.75,1690 595.75,1690 v1(645.75,1640)
  Top Layer L1 w9.84: v4(639.79,1221.48) 643.76,1217.51 U1.15@643.76,1111.12
  Bottom Layer L6 w9: v5@449.37,1740 R8.1@561.18,1851.81 ; v4(639.79,1221.48) 639.79,1634.04 v1(645.75,1640)
CLK: R5.1 U1.14 | length 802.3
  Top Layer L1 w9: U1.14@663.45,1111.12 663.45,1217.51 v4(667.41,1221.48)
  Bottom Layer L6 w9: v4(667.41,1221.48) 745.75,1299.81 v5(745.75,1740) 812.09,1806.34 R5.1@812.09,1851.81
